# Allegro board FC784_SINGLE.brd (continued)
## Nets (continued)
IO316: TP316.1(TP) U1.AD3(IO316)
IO317: TP317.1(TP) U1.AD4(IO317)
IO318: TP318.1(TP) U1.AD5(IO318)
IO319: TP319.1(TP) U1.AD6(IO319)
IO320: TP320.1(TP) U1.AD8(IO320)
IO321: TP321.1(TP) U1.AD9(IO321)
IO322: TP322.1(TP) U1.AD10(IO322)
IO323: TP323.1(TP) U1.AD11(IO323)
IO324: TP324.1(TP) U1.AD13(IO324)
IO325: TP325.1(TP) U1.AD14(IO325)
IO326: TP326.1(TP) U1.AD15(IO326)
IO327: TP327.1(TP) U1.AD16(IO327)
IO328: TP328.1(TP) U1.AD18(IO328)
IO329: TP329.1(TP) U1.AD19(IO329)
IO330: TP330.1(TP) U1.AD20(IO330)
IO331: TP331.1(TP) U1.AD21(IO331)
IO332: TP332.1(TP) U1.AE1(IO332)
IO333: TP333.1(TP) U1.AE2(IO333)
IO334: TP334.1(TP) U1.AE3(IO334)
IO335: TP335.1(TP) U1.AE5(IO335)
IO336: TP336.1(TP) U1.AE6(IO336)
IO337: TP337.1(TP) U1.AE7(IO337)
IO338: TP338.1(TP) U1.AE8(IO338)
IO339: TP339.1(TP) U1.AE10(IO339)
IO340: TP340.1(TP) U1.AE11(IO340)
IO341: TP341.1(TP) U1.AE12(IO341)
IO342: TP342.1(TP) U1.AE13(IO342)
IO343: TP343.1(TP) U1.AE15(IO343)
IO344: TP344.1(TP) U1.AE16(IO344)
IO345: TP345.1(TP) U1.AE17(IO345)
IO346: TP346.1(TP) U1.AE18(IO346)
IO347: TP347.1(TP) U1.AE20(IO347)
IO348: TP348.1(TP) U1.AE21(IO348)
IO349: TP349.1(TP) U1.AF1(IO349)
IO350: TP350.1(TP) U1.AF2(IO350)
IO351: TP351.1(TP) U1.AF3(IO351)
IO352: TP352.1(TP) U1.AF4(IO352)
IO353: TP353.1(TP) U1.AF5(IO353)
IO354: TP354.1(TP) U1.AF7(IO354)
IO355: TP355.1(TP) U1.AF8(IO355)
IO356: TP356.1(TP) U1.AF9(IO356)
IO357: TP357.1(TP) U1.AF10(IO357)
IO358: TP358.1(TP) U1.AF12(IO358)
IO359: TP359.1(TP) U1.AF13(IO359)
IO360: TP360.1(TP) U1.AF14(IO360)
IO361: TP361.1(TP) U1.AF15(IO361)
IO362: TP362.1(TP) U1.AF17(IO362)
IO363: TP363.1(TP) U1.AF18(IO363)
IO364: TP364.1(TP) U1.AF19(IO364)
IO365: TP365.1(TP) U1.AF20(IO365)
IO366: TP366.1(TP) U1.AG1(IO366)
IO367: TP367.1(TP) U1.AG2(IO367)
IO368: TP368.1(TP) U1.AG4(IO368)
IO369: TP369.1(TP) U1.AG5(IO369)
IO370: TP370.1(TP) U1.AG6(IO370)
IO371: TP371.1(TP) U1.AG7(IO371)
IO372: TP372.1(TP) U1.AG9(IO372)
IO373: TP373.1(TP) U1.AG10(IO373)
IO374: TP374.1(TP) U1.AG11(IO374)
IO375: TP375.1(TP) U1.AG12(IO375)
IO376: TP376.1(TP) U1.AG14(IO376)
IO377: TP377.1(TP) U1.AG15(IO377)
IO378: TP378.1(TP) U1.AG16(IO378)
IO379: TP379.1(TP) U1.AG17(IO379)
IO380: TP380.1(TP) U1.AG19(IO380)
IO381: TP381.1(TP) U1.AG20(IO381)
IO382: TP382.1(TP) U1.AG21(IO382)
IO383: TP383.1(TP) U1.AG22(IO383)
IO384: TP384.1(TP) U1.AH2(IO384)
IO385: TP385.1(TP) U1.AH3(IO385)
IO386: TP386.1(TP) U1.AH4(IO386)
IO387: TP387.1(TP) U1.AH6(IO387)
IO388: TP388.1(TP) U1.AH7(IO388)
IO389: TP389.1(TP) U1.AH8(IO389)
IO390: TP390.1(TP) U1.AH9(IO390)
IO391: TP391.1(TP) U1.AH11(IO391)
IO392: TP392.1(TP) U1.AH12(IO392)
IO393: TP393.1(TP) U1.AH13(IO393)
IO394: TP394.1(TP) U1.AH14(IO394)
IO395: TP395.1(TP) U1.AH16(IO395)
IO396: TP396.1(TP) U1.AH17(IO396)
IO397: TP397.1(TP) U1.AH18(IO397)
IO398: TP398.1(TP) U1.AH19(IO398)
IO399: TP399.1(TP) U1.AH21(IO399)
IO400: TP400.1(TP) U1.AH22(IO400)
IO401: TP401.1(TP) U1.AH23(IO401)
SERDES_0_INT_REFCLK_N: TP419.1(TP) U1.R24(SERDES_0_INT_REFCLK_N)
SERDES_0_INT_REFCLK_P: TP418.1(TP) U1.R23(SERDES_0_INT_REFCLK_P)
SERDES_0_RX0_N: TP403.1(TP) U1.T26(SERDES_0_RX0_N)
SERDES_0_RX0_P: TP402.1(TP) U1.T25(SERDES_0_RX0_P)
SERDES_0_RX1_N: TP405.1(TP) U1.V26(SERDES_0_RX1_N)
SERDES_0_RX1_P: TP404.1(TP) U1.V25(SERDES_0_RX1_P)
SERDES_0_RX2_N: TP407.1(TP) U1.Y26(SERDES_0_RX2_N)
SERDES_0_RX2_P: TP406.1(TP) U1.Y25(SERDES_0_RX2_P)
SERDES_0_RX3_N: TP409.1(TP) U1.AB26(SERDES_0_RX3_N)
SERDES_0_RX3_P: TP408.1(TP) U1.AB25(SERDES_0_RX3_P)
SERDES_0_TX0_N: TP411.1(TP) U1.R28(SERDES_0_TX0_N)
SERDES_0_TX0_P: TP410.1(TP) U1.R27(SERDES_0_TX0_P)
SERDES_0_TX1_N: TP412.1(TP) U1.U28(SERDES_0_TX1_N)
SERDES_0_TX1_P: TP413.1(TP) U1.U27(SERDES_0_TX1_P)
SERDES_0_TX2_N: TP415.1(TP) U1.W28(SERDES_0_TX2_N)
SERDES_0_TX2_P: TP414.1(TP) U1.W27(SERDES_0_TX2_P)
SERDES_0_TX3_N: TP417.1(TP) U1.AA28(SERDES_0_TX3_N)
SERDES_0_TX3_P: TP416.1(TP) U1.AA27(SERDES_0_TX3_P)
SERDES_0N_EXT_REFCLK_N: TP483.1(TP) U1.T22(SERDES_0N_EXT_REFCLK_N)
SERDES_0N_EXT_REFCLK_P: TP482.1(TP) U1.T21(SERDES_0N_EXT_REFCLK_P)
SERDES_0S_EXT_REFCLK_N: TP485.1(TP) U1.P22(SERDES_0S_EXT_REFCLK_N)
SERDES_0S_EXT_REFCLK_P: TP484.1(TP) U1.P21(SERDES_0S_EXT_REFCLK_P)
SERDES_01_EXT_REFCLK_N: TP475.1(TP) U1.N24(SERDES_01_EXT_REFCLK_N)
SERDES_01_EXT_REFCLK_P: TP474.1(TP) U1.N23(SERDES_01_EXT_REFCLK_P)
SERDES_1_INT_REFCLK_N: TP437.1(TP) U1.M22(SERDES_1_INT_REFCLK_N)
SERDES_1_INT_REFCLK_P: TP436.1(TP) U1.M21(SERDES_1_INT_REFCLK_P)
SERDES_1_RX0_N: TP421.1(TP) U1.H25(SERDES_1_RX0_N)
SERDES_1_RX0_P: TP420.1(TP) U1.H26(SERDES_1_RX0_P)
SERDES_1_RX1_N: TP422.1(TP) U1.K25(SERDES_1_RX1_N)
SERDES_1_RX1_P: TP423.1(TP) U1.K26(SERDES_1_RX1_P)
SERDES_1_RX2_N: TP425.1(TP) U1.M25(SERDES_1_RX2_N)
SERDES_1_RX2_P: TP424.1(TP) U1.M26(SERDES_1_RX2_P)
SERDES_1_RX3_N: TP427.1(TP) U1.P25(SERDES_1_RX3_N)
SERDES_1_RX3_P: TP426.1(TP) U1.P26(SERDES_1_RX3_P)
SERDES_1_TX0_N: TP429.1(TP) U1.G27(SERDES_1_TX0_N)
SERDES_1_TX0_P: TP428.1(TP) U1.G28(SERDES_1_TX0_P)
SERDES_1_TX1_N: TP430.1(TP) U1.J27(SERDES_1_TX1_N)
SERDES_1_TX1_P: TP431.1(TP) U1.J28(SERDES_1_TX1_P)
SERDES_1_TX2_N: TP433.1(TP) U1.L27(SERDES_1_TX2_N)
SERDES_1_TX2_P: TP432.1(TP) U1.L28(SERDES_1_TX2_P)
SERDES_1_TX3_N: TP435.1(TP) U1.N27(SERDES_1_TX3_N)
SERDES_1_TX3_P: TP434.1(TP) U1.N28(SERDES_1_TX3_P)
SERDES_02_EXT_REFCLK_N: TP476.1(TP) U1.U24(SERDES_02_EXT_REFCLK_N)
SERDES_02_EXT_REFCLK_P: TP477.1(TP) U1.U23(SERDES_02_EXT_REFCLK_P)
SERDES_2_INT_REFCLK_N: TP455.1(TP) U1.W24(SERDES_2_INT_REFCLK_N)
SERDES_2_INT_REFCLK_P: TP454.1(TP) U1.W23(SERDES_2_INT_REFCLK_P)
SERDES_2_RX0_N: TP439.1(TP) U1.AC23(SERDES_2_RX0_P)
SERDES_2_RX0_P: TP438.1(TP) U1.AC24(SERDES_2_RX0_N)
SERDES_2_RX1_N: TP440.1(TP) U1.AF26(SERDES_2_RX1_N)
SERDES_2_RX1_P: TP441.1(TP) U1.AF25(SERDES_2_RX1_P)
SERDES_2_RX2_N: TP443.1(TP) U1.AD26(SERDES_2_RX2_N)
SERDES_2_RX2_P: TP442.1(TP) U1.AD25(SERDES_2_RX2_P)
SERDES_2_RX3_N: TP445.1(TP) U1.AE24(SERDES_2_RX3_N)
SERDES_2_RX3_P: TP444.1(TP) U1.AE23(SERDES_2_RX3_P)
SERDES_2_TX0_N: TP447.1(TP) U1.AC28(SERDES_2_TX0_N)
SERDES_2_TX0_P: TP446.1(TP) U1.AC27(SERDES_2_TX0_P)
SERDES_2_TX1_N: TP448.1(TP) U1.AH26(SERDES_2_TX1_N)
SERDES_2_TX1_P: TP449.1(TP) U1.AH25(SERDES_2_TX1_P)
SERDES_2_TX2_N: TP451.1(TP) U1.AE28(SERDES_2_TX2_N)
SERDES_2_TX2_P: TP450.1(TP) U1.AE27(SERDES_2_TX2_P)
SERDES_2_TX3_N: TP453.1(TP) U1.AG28(SERDES_2_TX3_N)
SERDES_2_TX3_P: TP452.1(TP) U1.AG27(SERDES_2_TX3_P)
SERDES_3_INT_REFCLK_N: TP473.1(TP) U1.J24(SERDES_3_INT_REFCLK_N)
SERDES_3_INT_REFCLK_P: TP472.1(TP) U1.J23(SERDES_3_INT_REFCLK_P)
SERDES_3_RX0_N: TP457.1(TP) U1.B25(SERDES_3_RX0_N)
SERDES_3_RX0_P: TP456.1(TP) U1.B26(SERDES_3_RX0_P)
SERDES_3_RX1_N: TP458.1(TP) U1.D25(SERDES_3_RX1_N)
SERDES_3_RX1_P: TP459.1(TP) U1.D26(SERDES_3_RX1_P)
SERDES_3_RX2_N: TP461.1(TP) U1.C23(SERDES_3_RX2_N)
SERDES_3_RX2_P: TP460.1(TP) U1.C24(SERDES_3_RX2_P)
SERDES_3_RX3_N: TP463.1(TP) U1.F25(SERDES_3_RX3_N)
SERDES_3_RX3_P: TP462.1(TP) U1.F26(SERDES_3_RX3_P)
SERDES_3_TX0_N: TP465.1(TP) U1.A27(SERDES_3_TX0_N)
SERDES_3_TX0_P: TP464.1(TP) U1.A28(SERDES_3_TX0_P)
SERDES_3_TX1_N: TP466.1(TP) U1.C27(SERDES_3_TX1_N)
SERDES_3_TX1_P: TP467.1(TP) U1.C28(SERDES_3_TX1_P)
SERDES_3_TX2_N: TP469.1(TP) U1.A23(SERDES_3_TX2_N)
SERDES_3_TX2_P: TP468.1(TP) U1.A24(SERDES_3_TX2_P)
SERDES_3_TX3_N: TP471.1(TP) U1.E27(SERDES_3_TX3_N)
SERDES_3_TX3_P: TP470.1(TP) U1.E28(SERDES_3_TX3_P)
SERDES_13_EXT_REFCLK_N: TP479.1(TP) U1.L24(SERDES_13_EXT_REFCLK_N)
SERDES_13_EXT_REFCLK_P: TP478.1(TP) U1.L23(SERDES_13_EXT_REFCLK_P)
SERDES_24_EXT_REFCLK_N: TP487.1(TP) U1.AA24(SERDES_24_EXT_REFCLK_N)
SERDES_24_EXT_REFCLK_P: TP486.1(TP) U1.AA23(SERDES_24_EXT_REFCLK_P)
SERDES_35_EXT_REFCLK_N: TP488.1(TP) U1.G24(SERDES_35_EXT_REFCLK_N)
SERDES_35_EXT_REFCLK_P: TP489.1(TP) U1.G23(SERDES_35_EXT_REFCLK_P)
SERDES_VREF: U1.F22(SERDES_VREF1) U1.H22(SERDES_VREF2)

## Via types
v1: diameter 0.457, hole 0.254, TOP to BOTTOM, 643 vias

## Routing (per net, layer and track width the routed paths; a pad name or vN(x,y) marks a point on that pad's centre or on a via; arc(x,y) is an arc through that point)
GND: length 118.8
  TOP w0.254: U1.E25 v1(65.81,69.23) ; U1.AH24 v1(64.81,45.23) ; U1.J2 v1(41.81,65.23) ; U1.AH28 v1(68.81,45.23) ; U1.AA6 v1(45.81,52.23) ; U1.AB27 v1(67.81,51.23) ; U1.AG8 v1(47.81,46.23) ; U1.D28 v1(68.81,70.23) ; U1.AE4 v1(43.81,48.23) ; U1.K14 v1(53.81,64.23) ; U1.N13 v1(52.81,61.23) ; U1.A6 v1(46.31,73.44) ; U1.V18 v1(58.81,55.23) ; U1.Y9 v1(48.81,53.23) ; U1.V16 v1(56.81,55.23) ; U1.H5 v1(44.81,66.23) ; U1.D24 v1(64.81,70.23) ; U1.P12 v1(51.81,60.23) ; U1.AH27 v1(67.81,45.23) ; U1.T18 v1(58.81,57.23) ; U1.E14 v1(53.81,69.23) ; U1.AC20 v1(60.81,50.23) ; U1.P27 v1(67.81,60.23) ; U1.J25 v1(65.81,65.23) ; U1.V24 v1(64.81,55.23) ; U1.AE22 v1(62.81,48.23) ; U1.AD22 v1(62.81,49.23) ; U1.M14 v1(53.81,62.23) ; U1.V22 v1(62.81,55.23) ; U1.U13 v1(52.81,56.23) ; U1.U15 v1(55.81,56.23) ; U1.K24 v1(64.81,64.23) ; U1.E22 v1(62.81,69.23) ; U1.T24 v1(64.81,57.23) ; U1.V20 v1(60.81,55.23) ; U1.L11 v1(50.81,63.23) ; U1.K9 v1(48.81,64.23) ; U1.V27 v1(67.81,55.23) ; U1.U19 v1(59.81,56.23) ; U1.A16 v1(56.31,73.44) ; U1.L17 v1(57.81,63.23) ; U1.AG23 v1(62.81,46.23) ; U1.V21 v1(61.81,55.23) ; U1.U25 v1(65.81,56.23) ; U1.R25 v1(64.81,59.23) ; U1.AH5 v1(45.31,45.03) ; U1.AC10 v1(49.81,50.23) ; U1.F24 v1(64.81,68.23) ; U1.AF27 v1(67.81,47.23) ; U1.F1 v1(40.61,67.73) ; U1.Y27 v1(67.81,53.23) ; U1.L15 v1(55.81,63.23) ; U1.C20 v1(60.81,71.23) ; U1.AE14 v1(53.81,48.23) ; U1.M27 v1(67.81,62.23) ; U1.F11 v1(50.81,68.23) ; U1.B24 v1(64.81,72.23) ; U1.D22 v1(62.81,70.23) ; U1.AA16 v1(56.81,52.23) ; U1.K27 v1(67.81,64.23) ; U1.U11 v1(50.81,56.23) ; U1.N25 v1(65.81,61.23) ; U1.W22 v1(62.81,54.23) ; U1.D7 v1(46.81,70.23) ; U1.P7 v1(46.81,60.23) ; U1.AG25 v1(65.81,46.23) ; U1.P16 v1(56.81,60.23) ; U1.U17 v1(57.81,56.23) ; U1.R17 v1(56.81,59.23) ; U1.Y22 v1(62.81,53.23) ; U1.B3 v1(42.81,72.23) ; U1.AC22 v1(62.81,50.23) ; U1.AG24 v1(64.81,46.23) ; U1.F28 v1(68.81,68.23) ; U1.R19 v1(58.81,59.23) ; U1.A25 v1(64.81,73.23) ; U1.T20 v1(60.81,57.23) ; U1.AF11 v1(50.81,47.23) ; U1.AG18 v1(57.81,46.23) ; U1.M24 v1(64.81,62.23) ; U1.B13 v1(52.81,72.23) ; U1.B28 v1(68.81,72.23) ; U1.U8 v1(47.81,56.23) ; U1.T28 v1(68.81,57.23) ; U1.K20 v1(60.81,64.23) ; U1.AD17 v1(57.81,49.23) ; U1.E24 v1(64.81,69.23) ; U1.N22 v1(62.81,61.23) ; U1.AB24 v1(64.81,51.23) ; U1.M12 v1(51.81,62.23) ; U1.J22 v1(62.81,65.23) ; U1.T27 v1(67.81,57.23) ; U1.L25 v1(65.81,63.23) ; U1.L19 v1(59.81,63.23) ; U1.G8 v1(47.81,67.23) ; U1.K28 v1(68.81,64.23) ; U1.AB22 v1(62.81,51.23) ; U1.M18 v1(58.81,62.23) ; U1.R13 v1(52.81,58.23) ; U1.T14 v1(53.81,57.23) ; U1.H24 v1(64.81,66.23) ; U1.H27 v1(67.81,66.23) ; U1.Y24 v1(64.81,53.23) ; U1.W2 v1(41.81,54.23) ; U1.N19 v1(59.81,61.23) ; U1.G18 v1(58.81,67.23) ; U1.C10 v1(49.81,71.23) ; U1.E23 v1(63.81,69.23) ; U1.M16 v1(56.81,62.23) ; U1.AE25 v1(65.81,48.23) ; U1.V5 v1(44.81,55.23) ; U1.K21 v1(61.81,64.23) ; U1.F27 v1(67.81,68.23) ; U1.P20 v1(60.81,60.23) ; U1.W25 v1(65.81,54.23) ; U1.V28 v1(68.81,55.23) ; U1.AB13 v1(52.81,51.23) ; U1.AB28 v1(68.81,51.23) ; U1.V14 v1(53.81,55.23) ; U1.K22 v1(62.81,64.23) ; U1.N17 v1(57.81,61.23) ; U1.N11 v1(50.81,61.23) ; U1.AH15 v1(55.31,45.03) ; U1.R15 v1(54.81,59.23) ; U1.E4 v1(43.81,69.23) ; U1.C22 v1(62.81,71.23) ; U1.AD24 v1(64.81,49.23) ; U1.H28 v1(68.81,66.23) ; U1.H15 v1(55.81,66.23) ; U1.AD7 v1(46.81,49.23) ; U1.P14 v1(53.81,60.23) ; U1.AF21 v1(60.81,47.23) ; U1.M3 v1(42.81,62.23) ; U1.AB3 v1(42.81,51.23) ; U1.AF22 v1(61.81,47.23) ; U1.A22 v1(62.81,73.23) ; U1.T1 v1(40.61,57.73) ; U1.L13 v1(52.81,63.23) ; U1.R4 v1(43.81,58.23) ; U1.AD28 v1(68.81,49.23) ; U1.B27 v1(67.81,72.23) ; U1.M20 v1(60.81,62.23) ; U1.Y19 v1(59.81,53.23) ; U1.AF24 v1(64.81,47.23) ; U1.AD27 v1(67.81,49.23) ; U1.G25 v1(65.81,67.23) ; U1.D27 v1(67.81,70.23) ; U1.N15 v1(55.81,61.23) ; U1.G22 v1(62.81,67.23) ; U1.D17 v1(57.81,70.23) ; U1.V12 v1(51.81,55.23) ; U1.P18 v1(58.81,60.23) ; U1.L6 v1(45.81,63.23) ; U1.Y28 v1(68.81,53.23) ; U1.M28 v1(68.81,62.23) ; U1.R22 v1(61.81,59.23) ; U1.B22 v1(61.81,72.23) ; U1.AA22 v1(62.81,52.23) ; U1.AH1 v1(40.81,45.23) ; U1.AA25 v1(65.81,52.23) ; U1.R11 v1(50.81,58.23) ; U1.AC25 v1(65.81,50.23) ; U1.C25 v1(65.81,71.23) ; U1.AF28 v1(68.81,47.23) ; U1.A26 v1(65.81,73.23) ; U1.P28 v1(68.81,60.23) ; U1.T16 v1(56.81,57.23) ; U1.T12 v1(51.81,57.23)
VDD: length 14.8
  TOP w0.254: U1.M15 v1(55.81,62.23) ; U1.P15 v1(55.81,60.23) ; U1.P17 v1(57.81,60.23) ; U1.T19 v1(59.81,57.23) ; U1.P19 v1(59.81,60.23) ; U1.N16 v1(56.81,61.23) ; U1.T17 v1(57.81,57.23) ; U1.M19 v1(59.81,62.23) ; U1.U16 v1(56.81,56.23) ; U1.P13 v1(52.81,60.23) ; U1.T15 v1(55.81,57.23) ; U1.N20 v1(60.81,61.23) ; U1.R18 v1(57.81,59.23) ; U1.R20 v1(59.81,59.23) ; U1.T13 v1(52.81,57.23) ; U1.N18 v1(58.81,61.23) ; U1.U14 v1(53.81,56.23) ; U1.M17 v1(57.81,62.23) ; U1.N14 v1(53.81,61.23) ; U1.U18 v1(58.81,56.23) ; U1.R14 v1(53.81,58.23)
VDD18: length 4.2
  TOP w0.254: U1.V17 v1(57.81,55.23) ; U1.W21 v1(61.81,54.23) ; U1.V19 v1(59.81,55.23) ; U1.V15 v1(55.81,55.23) ; U1.W11 v1(50.81,54.23) ; U1.V13 v1(52.81,55.23)
VDD25: length 3.5
  TOP w0.254: U1.M13 v1(52.81,62.23) ; U1.L20 v1(60.81,63.23) ; U1.R16 v1(55.81,59.23) ; U1.U20 v1(60.81,56.23) ; U1.U12 v1(51.81,56.23)
VDDA: length 17
  TOP w0.254: U1.E26 v1(66.81,69.23) ; U1.T23 v1(63.81,57.23) ; U1.W26 v1(66.81,54.23) ; U1.AB23 v1(63.81,51.23) ; U1.AC26 v1(66.81,50.23) ; U1.B23 v1(62.81,72.23) ; U1.P24 v1(64.81,60.23) ; U1.C26 v1(66.81,71.23) ; U1.AA26 v1(66.81,52.23) ; U1.R26 v1(65.81,59.23) ; U1.H23 v1(63.81,66.23) ; U1.AD23 v1(63.81,49.23) ; U1.AF23 v1(62.81,47.23) ; U1.AE26 v1(66.81,48.23) ; U1.Y23 v1(63.81,53.23) ; U1.D23 v1(63.81,70.23) ; U1.G26 v1(66.81,67.23) ; U1.F23 v1(63.81,68.23) ; U1.U26 v1(66.81,56.23) ; U1.M23 v1(63.81,62.23) ; U1.N26 v1(66.81,61.23) ; U1.AG26 v1(66.81,46.23) ; U1.L26 v1(66.81,63.23) ; U1.J26 v1(66.81,65.23)
VDDA25: length 2.8
  TOP w0.254: U1.U22 v1(62.81,56.23) ; U1.N21 v1(61.81,61.23) ; U1.R21 v1(60.81,59.23) ; U1.L22 v1(62.81,63.23)
VDDAUX2: length 3.5
  TOP w0.254: U1.L16 v1(56.81,63.23) ; U1.K11 v1(50.81,64.23) ; U1.L14 v1(53.81,63.23) ; U1.K15 v1(55.81,64.23) ; U1.L18 v1(58.81,63.23)
VDDAUX4: length 2.8
  TOP w0.254: U1.V11 v1(50.81,55.23) ; U1.R12 v1(51.81,58.23) ; U1.P11 v1(50.81,60.23) ; U1.T11 v1(50.81,57.23)
VDDAUX5: length 2.1
  TOP w0.254: U1.M11 v1(50.81,62.23) ; U1.N12 v1(51.81,61.23) ; U1.L12 v1(51.81,63.23)
VDDI0: length 6.4
  TOP w0.254: U1.AE9 v1(48.81,48.23) ; U1.AG3 v1(42.81,46.23) ; U1.AC5 v1(44.81,50.23) ; U1.AA11 v1(50.81,52.23) ; U1.AD2 v1(41.81,49.23) ; U1.AF6 v1(45.81,47.23) ; U1.AH10 v1(50.31,45.03) ; U1.AA1 v1(40.61,52.73) ; U1.AB8 v1(47.81,51.23)
VDDI1: length 4.9
  TOP w0.254: U1.AF16 v1(55.81,47.23) ; U1.W17 v1(57.81,54.23) ; U1.AH20 v1(60.31,45.03) ; U1.AB18 v1(58.81,51.23) ; U1.AE19 v1(59.81,48.23) ; U1.AA21 v1(61.81,52.23) ; U1.AC15 v1(55.81,50.23)
VDDI2: length 8.5
  TOP w0.254: U1.A21 v1(61.81,73.23) ; U1.F16 v1(56.81,68.23) ; U1.B8 v1(47.81,72.23) ; U1.A11 v1(51.31,73.44) ; U1.D12 v1(51.81,70.23) ; U1.B18 v1(57.81,72.23) ; U1.E9 v1(48.81,69.23) ; U1.J17 v1(57.81,65.23) ; U1.G13 v1(52.81,67.23) ; U1.H20 v1(60.81,66.23) ; U1.E19 v1(59.81,69.23) ; U1.C15 v1(55.81,71.23)
VDDI3: length 1.4
  TOP w0.254: U1.H10 v1(49.81,66.23) ; U1.K13 v1(52.81,64.23)
VDDI4: length 7.8
  TOP w0.254: U1.U3 v1(42.81,56.23) ; U1.U10 v1(49.81,56.23) ; U1.R9 v1(48.81,58.23) ; U1.M8 v1(47.81,62.23) ; U1.W7 v1(46.81,54.23) ; U1.L1 v1(40.61,62.73) ; U1.T6 v1(45.81,57.23) ; U1.K4 v1(43.81,64.23) ; U1.P2 v1(41.81,60.23) ; U1.N5 v1(44.81,61.23) ; U1.Y4 v1(43.81,53.23)
VDDI5: length 4.2
  TOP w0.254: U1.J7 v1(46.81,65.23) ; U1.G3 v1(42.81,67.23) ; U1.F6 v1(45.81,68.23) ; U1.A1 v1(40.81,73.23) ; U1.C5 v1(44.81,71.23) ; U1.D2 v1(41.81,70.23)
VDDI7: length 2.1
  TOP w0.254: U1.AD12 v1(51.81,49.23) ; U1.AG13 v1(52.81,46.23) ; U1.Y14 v1(53.81,53.23)
VDDSREF: length 3.5
  TOP w0.254: U1.L21 v1(61.81,63.23) ; U1.U21 v1(61.81,56.23) ; U1.V23 v1(63.81,55.23) ; U1.K23 v1(63.81,64.23) ; U1.P23 v1(63.81,60.23)
IO1: length 1.6
  TOP w0.127: U1.A2 42.31,74.35
IO2: length 1.6
  TOP w0.127: U1.A3 43.31,74.35
IO3: length 1.6
  TOP w0.127: U1.A4 44.31,74.35
IO4: length 1.6
  TOP w0.127: U1.A5 45.31,74.35
IO5: length 1.6
  TOP w0.127: U1.A7 47.31,74.35
IO6: length 1.6
  TOP w0.127: U1.A8 48.31,74.35
IO7: length 1.6
  TOP w0.127: U1.A9 49.31,74.35
IO8: length 1.6
  TOP w0.127: U1.A10 50.31,74.35
IO9: length 1.6
  TOP w0.127: U1.A12 52.31,74.35
IO10: length 1.6
  TOP w0.127: U1.A13 53.31,74.35
IO11: length 1.6
  TOP w0.127: U1.A14 54.31,74.35
IO12: length 1.6
  TOP w0.127: U1.A15 55.31,74.35
IO13: length 1.6
  TOP w0.127: U1.A17 57.31,74.35
IO14: length 1.6
  TOP w0.127: U1.A18 58.31,74.35
IO15: length 1.6
  TOP w0.127: U1.A19 59.31,74.35
IO16: length 1.6
  TOP w0.127: U1.A20 60.31,74.35
IO17: length 1.9
  TOP w0.127: U1.B1 39.42,71.73
IO18: length 3.1
  TOP w0.127: 39.42,72.23 41.81,72.23 U1.B2
IO19: length 2.8
  TOP w0.127: 43.81,74.35 43.81,72.23 U1.B4
IO20: length 2.8
  TOP w0.127: U1.B5 44.81,72.23 44.81,74.35
IO21: length 2.8
  TOP w0.127: 45.81,74.33 45.81,72.23 U1.B6
IO22: length 2.8
  TOP w0.127: 46.81,74.33 46.81,72.23 U1.B7
IO23: length 2.8
  TOP w0.127: 48.81,74.35 48.81,72.23 U1.B9
IO24: length 2.8
  TOP w0.127: 49.81,74.35 49.81,72.23 U1.B10
IO25: length 2.9
  TOP w0.127: 50.81,74.39 50.81,72.24 U1.B11
IO26: length 2.8
  TOP w0.127: U1.B12 51.81,72.23 51.81,74.35
IO27: length 2.8
  TOP w0.127: U1.B14 53.81,72.23 53.81,74.35
IO28: length 2.8
  TOP w0.127: 54.81,74.35 54.81,72.23 U1.B15
IO29: length 2.8
  TOP w0.127: 55.81,74.35 55.81,72.23 U1.B16
IO30: length 2.8
  TOP w0.127: U1.B17 56.83,72.21 56.83,74.32
IO31: length 2.8
  TOP w0.127: U1.B19 58.81,72.23 58.81,74.35
IO32: length 2.8
  TOP w0.127: 59.81,74.35 59.81,72.23 U1.B20
IO33: length 2.8
  TOP w0.127: 60.81,74.35 60.81,72.23 U1.B21
IO34: length 1.9
  TOP w0.127: U1.C1 39.42,70.73
IO35: length 3.1
  TOP w0.127: U1.C2 41.81,71.23 39.42,71.23
IO36: length 3.1
  TOP w0.254: U1.C3 v1(42.81,71.23)
  L3_SIG1 w0.102: v1(42.81,71.23) 42.26,71.78 42.26,73.42
IO37: length 2.9
  TOP w0.254: U1.C4 v1(43.81,71.23)
  L3_SIG1 w0.102: v1(43.81,71.23) 43.81,73.42
IO38: length 3.5
  TOP w0.254: U1.C6 v1(45.81,71.23)
  L3_SIG1 w0.102: v1(45.81,71.23) 45.81,71.77 45.33,72.26 45.33,73.84
IO39: length 3.5
  TOP w0.254: U1.C7 v1(46.81,71.23)
  L3_SIG1 w0.102: v1(46.81,71.23) 46.81,74.02
IO40: length 3.5
  TOP w0.254: U1.C8 v1(47.81,71.23)
  L3_SIG1 w0.102: 48.31,73.79 48.31,71.73 v1(47.81,71.23)
IO41: length 3.3
  TOP w0.254: U1.C9 v1(48.81,71.23)
  L3_SIG1 w0.102: v1(48.81,71.23) 48.81,73.87
IO42: length 3.7
  TOP w0.254: U1.C11 v1(50.81,71.23)
  L3_SIG1 w0.102: v1(50.81,71.23) 50.81,72.04 50.3,72.55 50.3,74.04
IO43: length 3.5
  TOP w0.254: U1.C12 v1(51.81,71.23)
  L3_SIG1 w0.102: v1(51.81,71.23) 51.81,74.06
IO44: length 3.7
  TOP w0.254: U1.C13 v1(52.81,71.23)
  L3_SIG1 w0.102: 53.32,74.02 53.32,72.04 52.81,71.53 v1(52.81,71.23)
IO45: length 3.6
  TOP w0.254: U1.C14 v1(53.81,71.23)
  L3_SIG1 w0.102: 54.19,73.99 54.19,71.61 v1(53.81,71.23)
IO46: length 3.9
  TOP w0.254: U1.C16 v1(56.81,71.23)
  L3_SIG1 w0.102: 55.82,74.04 55.82,72.47 56.81,71.47 v1(56.81,71.23)
IO47: length 3.8
  TOP w0.254: U1.C17 v1(57.81,71.23)
  L3_SIG1 w0.102: 57.31,74.16 57.31,72 57.81,71.5 v1(57.81,71.23)
IO48: length 3.5
  TOP w0.254: U1.C18 v1(58.81,71.23)
  L3_SIG1 w0.102: v1(58.81,71.23) 58.81,74.01
IO49: length 2.9
  TOP w0.254: U1.C19 v1(59.81,71.23)
  L3_SIG1 w0.102: v1(59.81,71.23) 59.81,73.4
IO50: length 3.5
  TOP w0.254: U1.C21 v1(61.81,71.23)
  L3_SIG1 w0.102: v1(61.81,71.23) 61.81,71.53 61.28,72.06 61.28,73.78
IO51: length 1.9
  TOP w0.127: U1.D1 39.42,69.73
IO52: length 4.6
  TOP w0.254: U1.D3 v1(42.81,70.23)
  L3_SIG1 w0.102: 39.09,69.73 42.31,69.73 v1(42.81,70.23)
IO53: length 4.1
  TOP w0.254: U1.D4 v1(43.81,70.23)
  L3_SIG1 w0.102: v1(43.81,70.23) 43.81,70.52 43.31,71.02 43.31,73.45
IO54: length 3.9
  TOP w0.254: U1.D5 v1(44.81,70.23)
  L3_SIG1 w0.102: 44.31,73.27 44.31,70.73 v1(44.81,70.23)
IO55: length 4.7
  TOP w0.254: U1.D6 v1(45.81,70.23)
  L3_SIG1 w0.102: 45.8,73.85 45.8,72.5 46.31,71.99 46.31,70.73 v1(45.81,70.23)
IO56: length 4.6
  TOP w0.254: U1.D8 v1(47.81,70.23)
  L3_SIG1 w0.102: v1(47.81,70.23) 47.31,70.73 47.31,73.95
IO57: length 4.4
  TOP w0.254: U1.D9 v1(48.81,70.23)
  L3_SIG1 w0.102: v1(48.81,70.23) 49.31,70.73 49.31,73.74
IO58: length 4.9
  TOP w0.254: U1.D10 v1(49.81,70.23)
  L3_SIG1 w0.102: v1(49.81,70.23) 50.31,70.73 50.31,71.66 49.74,72.23 49.74,74.03
IO59: length 4.9
  TOP w0.254: U1.D11 v1(50.81,70.23)
  L3_SIG1 w0.102: v1(50.81,70.23) 51.31,70.73 51.31,72.47 50.79,72.98 50.79,74.03
IO60: length 4.8
  TOP w0.254: U1.D13 v1(52.81,70.23)
  L3_SIG1 w0.102: v1(52.81,70.23) 53.31,70.73 53.31,71.45 53.77,71.91 53.77,73.95
IO61: length 4.8
  TOP w0.254: U1.D14 v1(53.81,70.23)
  L3_SIG1 w0.102: 54.57,73.97 54.57,70.99 v1(53.81,70.23)
IO62: length 4.6
  TOP w0.254: U1.D15 v1(55.81,70.23)
  L3_SIG1 w0.102: 55,73.81 55,71.04 v1(55.81,70.23)
IO63: length 5.1
  TOP w0.254: U1.D16 v1(56.81,70.23)
  L3_SIG1 w0.102: 55.4,74.07 55.4,72.35 56.31,71.43 56.31,70.73 v1(56.81,70.23)
IO64: length 4.5
  TOP w0.254: U1.D18 v1(58.81,70.23)
  L3_SIG1 w0.102: 58.31,73.78 58.31,70.73 v1(58.81,70.23)
IO65: length 4.5
  TOP w0.254: U1.D19 v1(59.81,70.23)
  L3_SIG1 w0.102: 59.31,73.84 59.31,70.73 v1(59.81,70.23)
IO66: length 3.9
  TOP w0.254: U1.D20 v1(60.81,70.23)
  L3_SIG1 w0.102: 60.31,73.26 60.31,70.73 v1(60.81,70.23)
IO67: length 4.7
  TOP w0.254: U1.D21 v1(61.81,70.23)
  L3_SIG1 w0.102: v1(61.81,70.23) 61.31,70.73 61.31,71.44 60.71,72.04 60.71,73.77
IO68: length 1.9
  TOP w0.127: U1.E1 39.42,68.73
IO69: length 3.1
  TOP w0.127: 39.42,69.23 41.81,69.23 U1.E2
IO70: length 4.4
  TOP w0.254: U1.E3 v1(42.81,69.23)
  L3_SIG1 w0.102: v1(42.81,69.23) 39.09,69.23
IO71: length 7.3
  TOP w0.254: U1.E5 v1(44.81,69.23)
  L3_SIG1 w0.102: 39.1,70.73 43.02,70.73 43.31,70.45 43.31,70.03 43.61,69.73 44.31,69.73 44.8,69.23 v1(44.81,69.23)
IO72: length 5.6
  TOP w0.254: U1.E6 v1(45.81,69.23)
  L3_SIG1 w0.102: 44.89,73.75 44.89,72.04 45.32,71.62 45.32,69.73 v1(45.81,69.23)
IO73: length 7.5
  TOP w0.254: U1.E7 v1(46.81,69.23)
  L4_SIG2 w0.102: v1(46.81,69.23) 46.81,69.53 46.31,70.03 46.31,72.6 45.76,73.16 45.76,75.55
IO74: length 7.3
  TOP w0.254: U1.E8 v1(47.81,69.23)
  L4_SIG2 w0.102: v1(47.81,69.23) 47.31,69.73 47.31,75.64
IO75: length 7.3
  TOP w0.254: U1.E10 v1(49.81,69.23)
  L4_SIG2 w0.102: 49.31,75.64 49.31,69.73 v1(49.81,69.23)
IO76: length 7.5
  TOP w0.254: U1.E11 v1(50.81,69.23)
  L4_SIG2 w0.102: 50.63,75.53 50.63,73.15 51.31,72.47 51.31,69.73 v1(50.81,69.23)
IO77: length 5.7
  TOP w0.254: U1.E12 v1(51.81,69.23)
  L3_SIG1 w0.102: 52.31,74.05 52.31,69.73 v1(51.81,69.23)
IO78: length 7.3
  TOP w0.254: U1.E13 v1(52.81,69.23)
  L4_SIG2 w0.102: 53.31,75.64 53.31,69.73 v1(52.81,69.23)
IO79: length 7.3
  TOP w0.254: U1.E15 v1(55.81,69.23)
  L4_SIG2 w0.102: v1(55.81,69.23) 55.31,69.73 55.31,75.64
IO80: length 7.5
  TOP w0.254: U1.E16 v1(56.81,69.23)
  L4_SIG2 w0.102: v1(56.81,69.23) 56.31,69.73 56.31,72.62 56.86,73.16 56.86,75.54
IO81: length 5.9
  TOP w0.254: U1.E17 v1(57.81,69.23)
  L3_SIG1 w0.102: v1(57.81,69.23) 57.32,69.73 57.32,71.51 56.85,71.98 56.85,74.03
IO82: length 7.3
  TOP w0.254: U1.E18 v1(58.81,69.23)
  L4_SIG2 w0.102: 58.31,75.64 58.31,69.73 v1(58.81,69.23)
IO83: length 7.3
  TOP w0.254: U1.E20 v1(60.81,69.23)
  L4_SIG2 w0.102: v1(60.81,69.23) 60.31,69.73 60.31,75.64
IO84: length 5.9
  TOP w0.254: U1.E21 v1(61.81,69.23)
  L3_SIG1 w0.102: 62.31,74.24 62.31,69.73 v1(61.81,69.23)
IO85: length 3.1
  TOP w0.127: U1.F2 41.83,68.21 39.42,68.21
IO86: length 4.4
  TOP w0.254: U1.F3 v1(42.81,68.23)
  L3_SIG1 w0.102: v1(42.81,68.23) 39.11,68.23
IO87: length 5.6
  TOP w0.254: U1.F4 v1(43.81,68.23)
  L3_SIG1 w0.102: v1(43.81,68.23) 43.31,68.73 39.09,68.73
IO88: length 6.5
  TOP w0.254: U1.F5 v1(44.81,68.23)
  L4_SIG2 w0.102: v1(44.81,68.23) 44.52,68.23 44.02,68.73 39.26,68.73
IO89: length 9.5
  TOP w0.254: U1.F7 v1(46.81,68.23)
  L4_SIG2 w0.102: v1(46.81,68.23) 46.53,68.23 46.03,68.73 45.6,68.73 45.31,69.03 45.31,69.44 45.02,69.73 44.52,69.73 44.31,69.94 44.31,75.31
IO90: length 9.8
  TOP w0.254: U1.F8 v1(47.81,68.23)
  L4_SIG2 w0.102: 44.89,75.45 44.89,72.98 45.31,72.56 45.31,69.96 45.55,69.73 46.05,69.73 46.31,69.47 46.31,69.03 46.61,68.73 47.31,68.73 v1(47.81,68.23)
IO91: length 8.3
  TOP w0.254: U1.F9 v1(48.81,68.23)
  L4_SIG2 w0.102: v1(48.81,68.23) 48.31,68.73 48.31,75.64
IO92: length 8.3
  TOP w0.254: U1.F10 v1(49.81,68.23)
  L4_SIG2 w0.102: v1(49.81,68.23) 50.31,68.73 50.31,72.46 49.89,72.88 49.89,75.49
IO93: length 8.4
  TOP w0.254: U1.F12 v1(51.81,68.23)
  L4_SIG2 w0.102: v1(51.81,68.23) 52.31,68.73 52.31,75.67
IO94: length 8.4
  TOP w0.254: U1.F13 v1(52.81,68.23)
  L5_SIG3 w0.102: v1(52.81,68.23) 52.31,68.73 52.31,75.67
IO95: length 8.3
  TOP w0.254: U1.F14 v1(53.81,68.23)
  L4_SIG2 w0.102: 54.31,75.64 54.31,68.73 v1(53.81,68.23)
IO96: length 8.5
  TOP w0.254: U1.F15 v1(55.81,68.23)
  L4_SIG2 w0.102: v1(55.81,68.23) 54.98,69.07 54.98,75.64
IO97: length 8.3
  TOP w0.254: U1.F17 v1(57.81,68.23)
  L4_SIG2 w0.102: v1(57.81,68.23) 57.31,68.73 57.31,75.63
IO98: length 8.4
  TOP w0.254: U1.F18 v1(58.81,68.23)
  L5_SIG3 w0.102: 58.31,75.67 58.31,68.73 v1(58.81,68.23)
IO99: length 8.3
  TOP w0.254: U1.F19 v1(59.81,68.23)
  L4_SIG2 w0.102: v1(59.81,68.23) 59.31,68.73 59.31,75.64
IO100: length 6.9
  TOP w0.254: U1.F20 v1(60.81,68.23)
  L4_SIG2 w0.102: 61.31,74.2 61.31,68.73 v1(60.81,68.23)
IO101: length 8.3
  TOP w0.254: U1.F21 v1(61.81,68.23)
  L4_SIG2 w0.102: 62.31,75.65 62.31,68.73 v1(61.81,68.23)
IO102: length 1.9
  TOP w0.127: U1.G1 39.42,66.73
IO103: length 3.1
  TOP w0.127: 39.42,67.23 41.81,67.23 U1.G2
IO104: length 5.9
  TOP w0.254: U1.G4 v1(43.81,67.23)
  L3_SIG1 w0.102: v1(43.81,67.23) 43.31,67.73 42.21,67.73 41.64,67.17 39.09,67.17
IO105: length 6.5
  TOP w0.254: U1.G5 v1(44.81,67.23)
  L4_SIG2 w0.102: v1(44.81,67.23) 44.31,66.73 39.26,66.73
IO106: length 7.6
  TOP w0.254: U1.G6 v1(45.81,67.23)
  L4_SIG2 w0.102: 39.32,68.3 41.2,68.3 41.77,67.73 45.02,67.73 45.31,67.44 45.52,67.23 v1(45.81,67.23)
IO107: length 8.8
  TOP w0.254: U1.G7 v1(46.81,67.23)
  L4_SIG2 w0.102: v1(46.81,67.23) 46.31,67.73 45.61,67.73 45.31,68.03 45.31,68.49 45.07,68.73 44.56,68.73 44.31,68.98 44.31,69.44 44.02,69.73 40.27,69.73
IO108: length 8.4
  TOP w0.254: U1.G9 v1(48.81,67.23)
  L5_SIG3 w0.102: 48.31,74.67 48.31,68.02 48.81,67.52 v1(48.81,67.23)
IO109: length 8.2
  TOP w0.254: U1.G10 v1(49.81,67.23)
  L5_SIG3 w0.102: 49.31,74.5 49.31,67.73 v1(49.81,67.23)
IO110: length 8.4
  TOP w0.254: U1.G11 v1(50.81,67.23)
  L5_SIG3 w0.102: v1(50.81,67.23) 50.31,67.73 50.31,74.67
IO111: length 9.3
  TOP w0.254: U1.G12 v1(51.81,67.23)
  L5_SIG3 w0.102: v1(51.81,67.23) 51.31,67.73 51.31,72.24 51.85,72.78 51.85,75.4
IO112: length 9.5
  TOP w0.254: U1.G14 v1(53.81,67.23)
  L4_SIG2 w0.102: v1(53.81,67.23) 54.64,68.06 54.64,75.69
IO113: length 8.4
  TOP w0.254: U1.G15 v1(55.81,67.23)
  L5_SIG3 w0.102: 55.31,74.67 55.31,67.73 v1(55.81,67.23)
IO114: length 8.6
  TOP w0.254: U1.G16 v1(56.81,67.23)
  L5_SIG3 w0.102: 55.76,74.66 55.76,72.95 56.31,72.39 56.31,67.73 v1(56.81,67.23)
IO115: length 8.7
  TOP w0.254: U1.G17 v1(57.81,67.23)
  L5_SIG3 w0.102: 57.31,74.97 57.31,67.73 v1(57.81,67.23)
IO116: length 8.4
  TOP w0.254: U1.G19 v1(59.81,67.23)
  L5_SIG3 w0.102: 59.31,74.67 59.31,67.73 v1(59.81,67.23)
IO117: length 8.1
  TOP w0.254: U1.G20 v1(60.81,67.23)
  L5_SIG3 w0.102: 61.31,74.4 61.31,67.73 v1(60.81,67.23)
IO118: length 8.2
  TOP w0.254: U1.G21 v1(61.81,67.23)
  L5_SIG3 w0.102: 62.31,74.49 62.31,67.73 v1(61.81,67.23)
IO119: length 1.9
  TOP w0.127: U1.H1 39.42,65.73
IO120: length 3.1
  TOP w0.127: 39.42,66.23 41.81,66.23 U1.H2
IO121: length 4.4
  TOP w0.254: U1.H3 v1(42.81,66.23)
  L3_SIG1 w0.102: v1(42.81,66.23) 39.09,66.23
IO122: length 5.6
  TOP w0.254: U1.H4 v1(43.81,66.23)
  L3_SIG1 w0.102: v1(43.81,66.23) 43.31,66.73 39.09,66.73
IO123: length 8.4
  TOP w0.254: U1.H6 v1(45.81,66.23)
  L5_SIG3 w0.102: v1(45.81,66.23) 45.52,66.23 45.02,66.73 38.37,66.73
IO124: length 10
  TOP w0.254: U1.H7 v1(46.81,66.23)
  L5_SIG3 w0.102: 38.66,67.17 41.27,67.17 41.83,67.73 45.02,67.73 45.31,67.44 45.31,66.98 45.56,66.73 46.02,66.73 46.52,66.23 v1(46.81,66.23)
IO125: length 9.6
  TOP w0.254: U1.H8 v1(47.81,66.23)
  L5_SIG3 w0.102: v1(47.81,66.23) 47.54,66.23 47.04,66.73 46.61,66.73 46.31,67.03 46.31,67.44 46.02,67.73 45.61,67.73 45.31,68.03 45.31,68.44 45.02,68.73 40.48,68.73
IO126: length 9.8
  TOP w0.254: U1.H9 v1(48.81,66.23)
  L5_SIG3 w0.102: v1(48.81,66.23) 48.81,66.53 48.31,67.03 48.31,67.49 48.07,67.73 47.61,67.73 47.31,68.03 47.31,74.48
IO127: length 9.8
  TOP w0.254: U1.H11 v1(50.81,66.23)
  L6_SIG4 w0.102: 50.31,75.11 50.31,67.03 50.81,66.53 v1(50.81,66.23)
IO128: length 9.8
  TOP w0.254: U1.H12 v1(51.81,66.23)
  L6_SIG4 w0.102: v1(51.81,66.23) 52.31,66.73 52.31,75.11
IO129: length 9.4
  TOP w0.254: U1.H13 v1(52.81,66.23)
  L5_SIG3 w0.102: v1(52.81,66.23) 53.31,66.73 53.31,74.67
IO130: length 8.4
  TOP w0.254: U1.H14 v1(53.81,66.23)
  L5_SIG3 w0.102: v1(53.81,66.23) 54.31,66.73 54.31,73.67
IO131: length 9.4
  TOP w0.254: U1.H16 v1(56.81,66.23)
  L6_SIG4 w0.102: 55.65,74.42 55.65,72.86 56.31,72.19 56.31,66.73 v1(56.81,66.23)
IO132: length 7.7
  TOP w0.254: U1.H17 v1(57.81,66.23)
  L6_SIG4 w0.102: v1(57.81,66.23) 58.31,66.73 58.31,72.99
IO133: length 9.8
  TOP w0.254: U1.H18 v1(58.81,66.23)
  L6_SIG4 w0.102: v1(58.81,66.23) 58.81,66.51 59.31,67.01 59.31,75.11
IO134: length 7.6
  TOP w0.254: U1.H19 v1(59.81,66.23)
  L5_SIG3 w0.102: v1(59.81,66.23) 60.31,66.73 60.31,72.93
IO135: length 9.8
  TOP w0.254: U1.H21 v1(61.81,66.23)
  L5_SIG3 w0.102: v1(61.81,66.23) 62.31,66.73 63.02,66.73 63.31,67.03 63.31,74.29
IO136: length 1.9
  TOP w0.127: U1.J1 39.42,64.73
IO137: length 4.6
  TOP w0.254: U1.J3 v1(42.81,65.23)
  L3_SIG1 w0.102: v1(42.81,65.23) 42.31,64.73 39.1,64.73
IO138: length 5.6
  TOP w0.254: U1.J4 v1(43.81,65.23)
  L3_SIG1 w0.102: 39.09,65.73 43.31,65.73 v1(43.81,65.23)
IO139: length 6.5
  TOP w0.254: U1.J5 v1(44.81,65.23)
  L4_SIG2 w0.102: v1(44.81,65.23) 44.31,65.73 39.26,65.73
IO140: length 8.4
  TOP w0.254: U1.J6 v1(45.81,65.23)
  L5_SIG3 w0.102: v1(45.81,65.23) 45.31,65.73 38.37,65.73
IO141: length 7.5
  TOP w0.254: U1.J8 v1(47.81,65.23)
  L6_SIG4 w0.102: 41.26,65.73 47.11,65.73 47.6,65.23 v1(47.81,65.23)
IO142: length 11.6
  TOP w0.254: U1.J9 v1(48.81,65.23)
  L5_SIG3 w0.102: v1(48.81,65.23) 48.81,65.5 48.31,66 48.31,66.44 48.02,66.73 47.61,66.73 47.31,67.03 47.31,67.44 47.02,67.73 46.61,67.73 46.31,68.03 46.31,72.34 46.81,72.84 46.81,74.36
IO143: length 10.6
  TOP w0.254: U1.J10 v1(49.81,65.23)
  L6_SIG4 w0.102: v1(49.81,65.23) 49.81,65.52 49.31,66.02 49.31,66.44 49.02,66.73 48.61,66.73 48.31,67.03 48.31,74.22
IO144: length 11.4
  TOP w0.254: U1.J11 v1(50.81,65.23)
  L6_SIG4 w0.102: 49.31,75.07 49.31,67.03 49.61,66.73 50.02,66.73 50.31,66.44 50.31,65.73 v1(50.81,65.23)
IO145: length 11
  TOP w0.254: U1.J12 v1(51.81,65.23)
  L6_SIG4 w0.102: 50.67,75.02 50.67,72.8 51.31,72.16 51.31,65.73 v1(51.81,65.23)
IO146: length 10.9
  TOP w0.254: U1.J13 v1(52.81,65.23)
  L6_SIG4 w0.102: v1(52.81,65.23) 53.06,65.23 53.56,65.73 54.3,65.73 54.58,66.01 54.58,74.11
IO147: length 9.3
  TOP w0.254: U1.J14 v1(53.81,65.23)
  L5_SIG3 w0.102: v1(53.81,65.23) 54.64,66.06 54.64,73.5
IO148: length 10
  TOP w0.254: U1.J15 v1(55.81,65.23)
  L5_SIG3 w0.102: 54.82,74.11 54.97,73.96 54.97,66.07 v1(55.81,65.23)
IO149: length 10.4
  TOP w0.254: U1.J16 v1(56.81,65.23)
  L6_SIG4 w0.102: v1(56.81,65.23) 56.31,65.73 55.58,65.73 55.08,66.23 55.08,73.79
IO150: length 10.5
  TOP w0.254: U1.J18 v1(58.81,65.23)
  L6_SIG4 w0.102: v1(58.81,65.23) 58.81,65.52 59.31,66.02 59.31,66.44 59.61,66.73 60.02,66.73 60.31,67.03 60.31,74.13
IO151: length 10.3
  TOP w0.254: U1.J19 v1(59.81,65.23)
  L5_SIG3 w0.102: v1(59.81,65.23) 60.11,65.23 60.61,65.73 69.17,65.73
IO152: length 10
  TOP w0.254: U1.J20 v1(60.81,65.23)
  L4_SIG2 w0.102: v1(60.81,65.23) 61.31,64.73 69.91,64.73
IO153: length 10.4
  TOP w0.254: U1.J21 v1(61.81,65.23)
  L4_SIG2 w0.102: v1(61.81,65.23) 62.31,65.73 63.02,65.73 63.31,66.03 63.31,66.44 63.61,66.73 65.02,66.73 65.31,67.03 65.31,67.44 65.61,67.73 70.02,67.73
IO154: length 1.9
  TOP w0.127: U1.K1 39.42,63.73
IO155: length 3.1
  TOP w0.127: 39.42,64.23 41.81,64.23 U1.K2
IO156: length 4.3
  TOP w0.254: U1.K3 v1(42.81,64.23)
  L3_SIG1 w0.102: 39.25,64.23 v1(42.81,64.23)
IO157: length 6.5
  TOP w0.254: U1.K5 v1(44.81,64.23)
  L4_SIG2 w0.102: v1(44.81,64.23) 44.31,64.73 39.26,64.73
IO158: length 7.5
  TOP w0.254: U1.K6 v1(45.81,64.23)
  L4_SIG2 w0.102: 39.26,63.73 45.31,63.73 v1(45.81,64.23)
IO159: length 9.4
  TOP w0.254: U1.K7 v1(46.81,64.23)
  L5_SIG3 w0.102: v1(46.81,64.23) 46.31,64.73 38.37,64.73
IO160: length 8.8
  TOP w0.254: U1.K8 v1(47.81,64.23)
  L6_SIG4 w0.102: 39.91,64.73 47.33,64.73 47.81,64.24 v1(47.81,64.23)
IO161: length 12.3
  TOP w0.254: U1.K10 v1(49.81,64.23)
  L6_SIG4 w0.102: 47.31,74.31 47.31,67.03 47.61,66.73 48.02,66.73 48.31,66.44 48.31,66.03 48.61,65.73 49.02,65.73 49.31,65.44 49.31,64.73 v1(49.81,64.23)
IO162: length 12.4
  TOP w0.254: U1.K12 v1(51.81,64.23)
  L6_SIG4 w0.102: v1(51.81,64.23) 52.31,64.73 52.31,65.44 52.61,65.73 53.02,65.73 53.31,66.03 53.31,75.11
IO163: length 11.5
  TOP w0.254: U1.K16 v1(56.81,64.23)
  L6_SIG4 w0.102: 57.31,74.84 57.31,64.73 v1(56.81,64.23)
IO164: length 13.3
  TOP w0.254: U1.K17 v1(57.81,64.23)
  L6_SIG4 w0.102: 61.31,74.47 61.31,67.03 61.02,66.73 60.61,66.73 60.31,66.44 60.31,65.94 60.1,65.73 59.61,65.73 59.31,65.44 59.31,65.03 59.02,64.73 58.29,64.73 57.81,64.26 v1(57.81,64.23)
IO165: length 10.6
  TOP w0.254: U1.K18 v1(58.81,64.23)
  L5_SIG3 w0.102: 68.54,63.73 59.31,63.73 v1(58.81,64.23)
IO166: length 10.1
  TOP w0.254: U1.K19 v1(59.81,64.23)
  L5_SIG3 w0.102: v1(59.81,64.23) 60.31,64.73 69.01,64.73
IO167: length 3.1
  TOP w0.127: U1.L2 41.82,63.23 39.47,63.23
IO168: length 4.3
  TOP w0.254: U1.L3 v1(42.81,63.23)
  L3_SIG1 w0.102: v1(42.81,63.23) 39.21,63.23
IO169: length 5.8
  TOP w0.254: U1.L4 v1(43.81,63.23)
  L3_SIG1 w0.102: 39.14,62.17 41.96,62.17 42.52,62.73 43.31,62.73 v1(43.81,63.23)
IO170: length 6.5
  TOP w0.254: U1.L5 v1(44.81,63.23)
  L3_SIG1 w0.102: v1(44.81,63.23) 44.32,63.73 39.19,63.73
IO171: length 8.4
  TOP w0.254: U1.L7 v1(46.81,63.23)
  L5_SIG3 w0.102: 39.37,63.73 46.31,63.73 v1(46.81,63.23)
IO172: length 9.5
  TOP w0.254: U1.L8 v1(47.81,63.23)
  L6_SIG4 w0.102: 39.25,63.73 47.31,63.73 v1(47.81,63.23)
IO173: length 11.4
  TOP w0.254: U1.L9 v1(48.81,63.23)
  L6_SIG4 w0.102: 40.78,66.73 47.02,66.73 47.31,66.44 47.31,66.03 47.61,65.73 48.02,65.73 48.31,65.44 48.31,63.73 v1(48.81,63.23)
IO174: length 0.7
  TOP w0.254: U1.L10 v1(49.81,63.23)
  L6_SIG4 w0.102: 49.81,63.26 v1(49.81,63.23)
IO175: length 1.9
  TOP w0.127: U1.M1 39.42,61.73
IO176: length 3.1
  TOP w0.127: 39.42,62.23 41.81,62.23 U1.M2
IO177: length 5.6
  TOP w0.254: U1.M4 v1(43.81,62.23)
  L3_SIG1 w0.102: v1(43.81,62.23) 43.31,61.73 39.14,61.73
IO178: length 6.6
  TOP w0.254: U1.M5 v1(44.81,62.23)
  L4_SIG2 w0.102: v1(44.81,62.23) 44.31,62.73 41.56,62.73 41.07,63.23 39.32,63.23
IO179: length 7.6
  TOP w0.254: U1.M6 v1(45.81,62.23)
  L5_SIG3 w0.102: v1(45.81,62.23) 45.31,62.73 41.47,62.73 40.87,62.13 39.34,62.13
IO180: length 8.4
  TOP w0.254: U1.M7 v1(46.81,62.23)
  L5_SIG3 w0.102: 39.37,61.73 46.31,61.73 v1(46.81,62.23)
IO181: length 11
  TOP w0.254: U1.M9 v1(48.81,62.23)
  L6_SIG4 w0.102: v1(48.81,62.23) 48.31,62.73 41.55,62.73 41,63.28 38.99,63.28
IO182: length 11.8
  TOP w0.254: U1.M10 v1(49.81,62.23)
  L6_SIG4 w0.102: 38.93,61.73 49.31,61.73 v1(49.81,62.23)
IO183: length 1.9
  TOP w0.127: U1.N1 39.42,60.73
IO184: length 3.1
  TOP w0.127: 39.42,61.23 41.81,61.23 U1.N2
IO185: length 4.4
  TOP w0.254: U1.N3 v1(42.81,61.23)
  L3_SIG1 w0.102: v1(42.81,61.23) 39.14,61.23
IO186: length 5.6
  TOP w0.254: U1.N4 v1(43.81,61.23)
  L3_SIG1 w0.102: v1(43.81,61.23) 43.31,60.73 39.14,60.73
IO187: length 7.5
  TOP w0.254: U1.N6 v1(45.81,61.23)
  L4_SIG2 w0.102: 39.26,61.73 45.31,61.73 v1(45.81,61.23)
IO188: length 9.1
  TOP w0.254: U1.N7 v1(46.81,61.23)
  L4_SIG2 w0.102: v1(46.81,61.23) 46.31,60.73 46.31,59.72 46,59.4 39.8,59.4
IO189: length 8.4
  TOP w0.254: U1.N8 v1(47.81,61.23)
  L5_SIG3 w0.102: 40.37,60.73 47.31,60.73 v1(47.81,61.23)
IO190: length 9.8
  TOP w0.254: U1.N9 v1(48.81,61.23)
  L6_SIG4 w0.102: v1(48.81,61.23) 48.31,60.73 39.93,60.73
IO191: length 10.1
  TOP w0.254: U1.N10 v1(49.81,61.23)
  L6_SIG4 w0.102: v1(49.81,61.23) 49.31,60.73 49.31,60.03 49.01,59.72 41.42,59.72
IO192: length 1.8
  TOP w0.127: U1.P1 39.5,59.73
IO193: length 4.5
  TOP w0.254: U1.P3 v1(42.81,60.23)
  L3_SIG1 w0.102: v1(42.81,60.23) 42.3,59.72 39.25,59.72
IO194: length 5.6
  TOP w0.254: U1.P4 v1(43.81,60.23)
  L3_SIG1 w0.102: 39.3,59.21 42.79,59.21 v1(43.81,60.23)
IO195: length 6.5
  TOP w0.254: U1.P5 v1(44.81,60.23)
  L4_SIG2 w0.102: v1(44.81,60.23) 44.31,60.73 39.26,60.73
IO196: length 7.5
  TOP w0.254: U1.P6 v1(45.81,60.23)
  L4_SIG2 w0.102: 39.26,59.73 45.31,59.73 v1(45.81,60.23)
IO197: length 8.4
  TOP w0.254: U1.P8 v1(47.81,60.23)
  L5_SIG3 w0.102: 40.37,59.72 47.3,59.72 v1(47.81,60.23)
IO198: length 9.5
  TOP w0.254: U1.P9 v1(48.81,60.23)
  L5_SIG3 w0.102: v1(48.81,60.23) 47.97,59.39 40.41,59.39
IO199: length 9.7
  TOP w0.254: U1.P10 v1(49.81,60.23)
  L6_SIG4 w0.102: v1(49.81,60.23) 49.81,59.99 49.21,59.39 41.27,59.39
IO200: length 1.8
  TOP w0.127: U1.R1 39.5,58.73
IO201: length 3
  TOP w0.127: U1.R2 41.81,59.23 39.5,59.23
IO202: length 4.3
  TOP w0.254: U1.R3 v1(42.81,58.23)
  L3_SIG1 w0.102: v1(42.81,58.23) 39.25,58.23
IO203: length 6.5
  TOP w0.254: U1.R5 v1(44.81,58.23)
  L3_SIG1 w0.102: 39.29,58.79 44.26,58.79 v1(44.81,58.23)
IO204: length 7.5
  TOP w0.254: U1.R6 v1(45.81,58.23)
  L4_SIG2 w0.102: v1(45.81,58.23) 45.31,58.73 39.26,58.73
IO205: length 8.4
  TOP w0.254: U1.R7 v1(46.81,58.23)
  L4_SIG2 w0.102: 39.46,59.07 45.98,59.07 v1(46.81,58.23)
IO206: length 8.3
  TOP w0.254: U1.R8 v1(47.81,58.23)
  L5_SIG3 w0.102: v1(47.81,58.23) 47.31,58.73 40.47,58.73
IO207: length 10.6
  TOP w0.254: U1.R10 v1(49.81,58.23)
  L6_SIG4 w0.102: 40.58,59.06 49.46,59.06 49.81,58.71 v1(49.81,58.23)
IO208: length 3
  TOP w0.127: U1.T2 41.81,58.23 39.5,58.23
IO209: length 4
  TOP w0.127: U1.T3 42.83,57.25 39.52,57.25
IO210: length 5.6
  TOP w0.254: U1.T4 v1(43.81,57.23)
  L3_SIG1 w0.102: 39.14,56.78 41.61,56.78 42.06,57.23 v1(43.81,57.23)
IO211: length 6.8
  TOP w0.254: U1.T5 v1(44.81,57.23)
  L3_SIG1 w0.102: 39.17,57.22 41.08,57.22 41.59,57.73 44.32,57.73 v1(44.81,57.23)
IO212: length 8.5
  TOP w0.254: U1.T7 v1(46.81,57.23)
  L4_SIG2 w0.102: 39.44,58.23 40.98,58.23 41.48,57.73 46.31,57.73 v1(46.81,57.23)
IO213: length 9.9
  TOP w0.254: U1.T8 v1(47.81,57.23)
  L5_SIG3 w0.102: v1(47.81,57.23) 47.31,57.73 41.87,57.73 41.32,57.19 39.03,57.19
IO214: length 10.5
  TOP w0.254: U1.T9 v1(48.81,57.23)
  L5_SIG3 w0.102: v1(48.81,57.23) 48.31,57.73 48.31,58.72 47.97,59.06 40.34,59.06
IO215: length 10.8
  TOP w0.254: U1.T10 v1(49.81,57.23)
  L6_SIG4 w0.102: 40.76,58.73 49.02,58.73 49.31,58.44 49.31,57.73 v1(49.81,57.23)
IO216: length 1.8
  TOP w0.127: U1.U1 39.5,56.73
IO217: length 3
  TOP w0.127: U1.U2 41.81,56.23 39.5,56.23
IO218: length 5.9
  TOP w0.254: U1.U4 v1(43.81,56.23)
  L3_SIG1 w0.102: 39.02,56.3 41.97,56.3 42.39,56.73 43.31,56.73 v1(43.81,56.23)
IO219: length 6.5
  TOP w0.254: U1.U5 v1(44.81,56.23)
  L4_SIG2 w0.102: 39.26,56.73 44.31,56.73 v1(44.81,56.23)
IO220: length 7.4
  TOP w0.254: U1.U6 v1(45.81,56.23)
  L4_SIG2 w0.102: 39.36,55.73 45.31,55.73 v1(45.81,56.23)
IO221: length 9.4
  TOP w0.254: U1.U7 v1(46.81,56.23)
  L5_SIG3 w0.102: v1(46.81,56.23) 46.31,56.73 38.37,56.73
IO222: length 11.6
  TOP w0.254: U1.U9 v1(48.81,56.23)
  L6_SIG4 w0.102: v1(48.81,56.23) 48.31,56.73 48.31,57.44 48.02,57.73 41.87,57.73 41.26,57.12 39.24,57.12
IO223: length 1.8
  TOP w0.127: U1.V1 39.5,55.73
IO224: length 3
  TOP w0.127: 39.5,55.23 41.81,55.23 U1.V2
IO225: length 4.5
  TOP w0.254: U1.V3 v1(42.81,55.23)
  L3_SIG1 w0.102: v1(42.81,55.23) 39.05,55.23
IO226: length 5.7
  TOP w0.254: U1.V4 v1(43.81,55.23)
  L3_SIG1 w0.102: v1(43.81,55.23) 43.31,55.73 39.01,55.73
IO227: length 8.4
  TOP w0.254: U1.V6 v1(45.81,55.23)
  L5_SIG3 w0.102: v1(45.81,55.23) 45.31,55.73 38.37,55.73
IO228: length 8.4
  TOP w0.254: U1.V7 v1(46.81,55.23)
  L5_SIG3 w0.102: 39.37,54.73 46.31,54.73 v1(46.81,55.23)
IO229: length 9.8
  TOP w0.254: U1.V8 v1(47.81,55.23)
  L6_SIG4 w0.102: v1(47.81,55.23) 47.64,55.23 47.14,55.73 38.93,55.73
IO230: length 11.1
  TOP w0.254: U1.V9 v1(48.81,55.23)
  L6_SIG4 w0.102: v1(48.81,55.23) 48.31,55.73 47.61,55.73 47.31,56.03 47.31,56.44 47.02,56.73 39.26,56.73
IO231: length 9.8
  TOP w0.254: U1.V10 v1(49.81,55.23)
  L6_SIG4 w0.102: v1(49.81,55.23) 49.31,54.73 40.91,54.73
IO232: length 1.8
  TOP w0.127: U1.W1 39.5,54.73
IO233: length 4.6
  TOP w0.254: U1.W3 v1(42.81,54.23)
  L3_SIG1 w0.102: 39.11,53.73 42.31,53.73 v1(42.81,54.23)
IO234: length 5.7
  TOP w0.254: U1.W4 v1(43.81,54.23)
  L3_SIG1 w0.102: 38.98,54.73 43.31,54.73 v1(43.81,54.23)
IO235: length 6.5
  TOP w0.254: U1.W5 v1(44.81,54.23)
  L4_SIG2 w0.102: v1(44.81,54.23) 44.31,54.73 39.26,54.73
IO236: length 7.5
  TOP w0.254: U1.W6 v1(45.81,54.23)
  L4_SIG2 w0.102: 39.23,53.73 45.31,53.73 v1(45.81,54.23)
IO237: length 9.1
  TOP w0.254: U1.W8 v1(47.81,54.23)
  L5_SIG3 w0.102: 39.61,53.73 47.31,53.73 v1(47.81,54.23)
IO238: length 11.8
  TOP w0.254: U1.W9 v1(48.81,54.23)
  L6_SIG4 w0.102: v1(48.81,54.23) 48.55,54.23 48.04,53.73 37.93,53.73
IO239: length 12.2
  TOP w0.254: U1.W10 v1(49.81,54.23)
  L6_SIG4 w0.102: 45.31,45.78 45.31,50.44 45.61,50.73 46.02,50.73 46.31,51.03 46.31,51.44 46.61,51.73 47.02,51.73 47.31,52.03 47.31,52.44 47.61,52.73 48.02,52.73 48.31,53.03 48.31,53.44 48.61,53.73 49.31,53.73 v1(49.81,54.23)
IO240: length 12.5
  TOP w0.254: U1.W12 v1(51.81,54.23)
  L6_SIG4 w0.102: 47.31,45.47 47.31,50.44 47.61,50.73 48.02,50.73 48.31,51.03 48.31,51.44 48.61,51.73 49.02,51.73 49.31,52.03 49.31,52.44 49.61,52.73 50.05,52.73 50.31,52.99 50.31,53.44 50.61,53.73 51.31,53.73 v1(51.81,54.23)
IO241: length 9.3
  TOP w0.254: U1.W13 v1(52.81,54.23)
  L6_SIG4 w0.102: v1(52.81,54.23) 52.31,53.73 52.31,45.83
IO242: length 9.4
  TOP w0.254: U1.W14 v1(53.81,54.23)
  L6_SIG4 w0.102: v1(53.81,54.23) 54.33,53.72 54.33,48.34 54.31,48.33 54.31,45.78
IO243: length 10.3
  TOP w0.254: U1.W15 v1(55.81,54.23)
  L6_SIG4 w0.102: 57.31,45.46 57.31,50.44 57.02,50.73 56.61,50.73 56.31,51.03 56.31,53.73 v1(55.81,54.23)
IO244: length 15.4
  TOP w0.254: U1.W16 v1(56.81,54.23)
  L5_SIG3 w0.102: 69.63,56.73 58.61,56.73 58.31,56.44 58.31,55.03 58.02,54.73 57.31,54.73 v1(56.81,54.23)
IO245: length 12.7
  TOP w0.254: U1.W18 v1(58.81,54.23)
  L5_SIG3 w0.102: 69.73,55.73 59.58,55.73 59.31,55.46 59.31,54.73 v1(58.81,54.23)
IO246: length 10.7
  TOP w0.254: U1.W19 v1(59.81,54.23)
  L5_SIG3 w0.102: v1(59.81,54.23) 60.31,54.73 69.61,54.73
IO247: length 10
  TOP w0.254: U1.W20 v1(60.81,54.23)
  L4_SIG2 w0.102: 69.93,53.73 61.31,53.73 v1(60.81,54.23)
IO248: length 1.8
  TOP w0.127: U1.Y1 39.5,53.73
IO249: length 3
  TOP w0.127: U1.Y2 41.81,53.23 39.5,53.23
IO250: length 4.4
  TOP w0.254: U1.Y3 v1(42.81,53.23)
  L3_SIG1 w0.102: v1(42.81,53.23) 39.11,53.23
IO251: length 6.8
  TOP w0.254: U1.Y5 v1(44.81,53.23)
  L3_SIG1 w0.102: 39.12,52.24 41.19,52.24 41.69,52.74 44.32,52.74 v1(44.81,53.23)
IO252: length 7.6
  TOP w0.254: U1.Y6 v1(45.81,53.23)
  L5_SIG3 w0.102: 39.39,52.09 40.9,52.09 41.55,52.73 45.02,52.73 45.52,53.23 v1(45.81,53.23)
IO253: length 9
  TOP w0.254: U1.Y7 v1(46.81,53.23)
  L5_SIG3 w0.102: 39.46,51.43 41.34,51.43 41.65,51.73 45.02,51.73 45.31,52.03 45.31,52.44 45.61,52.73 46.31,52.73 v1(46.81,53.23)
IO254: length 10.1
  TOP w0.254: U1.Y8 v1(47.81,53.23)
  L6_SIG4 w0.102: v1(47.81,53.23) 47.55,53.23 47.04,52.73 41.55,52.73 40.87,52.05 38.91,52.05
IO255: length 11
  TOP w0.254: U1.Y10 v1(49.81,53.23)
  L6_SIG4 w0.102: v1(49.81,53.23) 49.6,53.23 49.1,52.73 48.61,52.73 48.31,52.44 48.31,51.94 48.1,51.73 47.61,51.73 47.31,51.44 47.31,51.03 47.02,50.73 46.61,50.73 46.31,50.44 46.31,45.35
IO256: length 10.5
  TOP w0.254: U1.Y11 v1(50.81,53.23)
  L6_SIG4 w0.102: 48.31,44.98 48.31,50.44 48.61,50.73 49.02,50.73 49.31,51.03 49.31,51.44 49.61,51.73 50.02,51.73 50.31,52.03 50.31,52.47 50.81,52.97 v1(50.81,53.23)
IO257: length 9.8
  TOP w0.254: U1.Y12 v1(51.81,53.23)
  L6_SIG4 w0.102: 49.31,45.8 49.31,50.44 49.61,50.73 50.02,50.73 50.31,51.03 50.31,51.52 50.52,51.73 51.11,51.73 51.31,51.94 51.31,52.73 v1(51.81,53.23)
IO258: length 8.3
  TOP w0.254: U1.Y13 v1(52.81,53.23)
  L6_SIG4 w0.102: v1(52.81,53.23) 53.31,52.73 53.31,45.83
IO259: length 8.5
  TOP w0.254: U1.Y15 v1(55.81,53.23)
  L6_SIG4 w0.102: 55.31,46.02 55.31,49.56 54.83,50.05 54.83,52.25 v1(55.81,53.23)
IO260: length 9.3
  TOP w0.254: U1.Y16 v1(56.81,53.23)
  L6_SIG4 w0.102: v1(56.81,53.23) 57.31,52.73 57.31,51.03 57.61,50.73 58.02,50.73 58.31,50.44 58.31,45.46
IO261: length 12.8
  TOP w0.254: U1.Y17 v1(57.81,53.23)
  L5_SIG3 w0.102: v1(57.81,53.23) 58.31,53.73 69.74,53.73
IO262: length 11.9
  TOP w0.254: U1.Y18 v1(58.81,53.23)
  L5_SIG3 w0.102: v1(58.81,53.23) 59.31,52.74 69.76,52.74
IO263: length 12.3
  TOP w0.254: U1.Y20 v1(60.81,53.23)
  L4_SIG2 w0.102: v1(60.81,53.23) 61.31,52.73 62.02,52.73 62.31,52.44 62.31,52.03 62.61,51.73 64.02,51.73 64.31,51.44 64.31,51.02 64.61,50.73 65.02,50.73 65.31,50.44 65.31,50.01 65.59,49.73 70.22,49.73
IO264: length 9.1
  TOP w0.254: U1.Y21 v1(61.81,53.23)
  L4_SIG2 w0.102: 69.97,52.73 62.52,52.73 62.02,53.23 v1(61.81,53.23)
IO265: length 3
  TOP w0.127: 39.53,52.25 41.83,52.25 U1.AA2
IO266: length 4.6
  TOP w0.254: U1.AA3 v1(42.81,52.23)
  L3_SIG1 w0.102: v1(42.81,52.23) 41.97,52.23 41.47,51.72 39.11,51.72
IO267: length 5.8
  TOP w0.254: U1.AA4 v1(43.81,52.23)
  L3_SIG1 w0.102: v1(43.81,52.23) 43.31,51.73 42.52,51.73 42,51.21 39.11,51.21
IO268: length 6.7
  TOP w0.254: U1.AA5 v1(44.81,52.23)
  L4_SIG2 w0.102: v1(44.81,52.23) 44.31,52.73 41.5,52.73 40.99,53.24 39.27,53.24
IO269: length 8.7
  TOP w0.254: U1.AA7 v1(46.81,52.23)
  L5_SIG3 w0.102: v1(46.81,52.23) 46.52,52.23 46.02,51.73 45.61,51.73 45.31,51.44 45.31,51.03 45.02,50.73 39.64,50.73
IO270: length 8.9
  TOP w0.254: U1.AA8 v1(47.81,52.23)
  L5_SIG3 w0.102: v1(47.81,52.23) 47.52,52.23 47.02,51.73 46.61,51.73 46.31,51.44 46.31,51.03 46.02,50.73 45.61,50.73 45.31,50.44 45.31,45.71
IO271: length 9.5
  TOP w0.254: U1.AA9 v1(48.81,52.23)
  L5_SIG3 w0.102: v1(48.81,52.23) 48.52,52.23 48.02,51.73 47.52,51.73 47.31,51.52 47.31,51.03 47.02,50.73 46.61,50.73 46.31,50.44 46.31,45.22
IO272: length 10
  TOP w0.254: U1.AA10 v1(49.81,52.23)
  L5_SIG3 w0.102: v1(49.81,52.23) 49.31,51.73 48.61,51.73 48.31,51.44 48.31,51.03 48.02,50.73 47.59,50.73 47.31,50.46 47.31,44.6
IO273: length 8.3
  TOP w0.254: U1.AA12 v1(51.81,52.23)
  L6_SIG4 w0.102: v1(51.81,52.23) 51.81,51.94 51.31,51.44 51.31,51.24 51.31,51.23 51.31,44.83
IO274: length 10.4
  TOP w0.254: U1.AA13 v1(52.81,52.23)
  L5_SIG3 w0.102: v1(52.81,52.23) 52.31,51.73 52.31,42.79
IO275: length 10.4
  TOP w0.254: U1.AA14 v1(53.81,52.23)
  L5_SIG3 w0.102: v1(53.81,52.23) 53.31,51.73 53.31,42.79
IO276: length 8.3
  TOP w0.254: U1.AA15 v1(55.81,52.23)
  L6_SIG4 w0.102: v1(55.81,52.23) 55.31,51.73 55.31,51.03 55.61,50.73 56.02,50.73 56.31,50.44 56.31,45.53
IO277: length 8.4
  TOP w0.254: U1.AA17 v1(57.81,52.23)
  L6_SIG4 w0.102: v1(57.81,52.23) 58.31,51.73 59.02,51.73 59.31,51.44 59.31,45.6
IO278: length 8.3
  TOP w0.254: U1.AA18 v1(58.81,52.23)
  L6_SIG4 w0.102: v1(58.81,52.23) 58.99,52.23 59.49,51.73 60.02,51.73 60.31,51.44 60.31,45.68
IO279: length 9.7
  TOP w0.254: U1.AA19 v1(59.81,52.23)
  L5_SIG3 w0.102: 61.31,44.09 61.31,49.44 61.02,49.73 60.61,49.73 60.31,50.03 60.31,51.73 v1(59.81,52.23)
IO280: length 12.4
  TOP w0.254: U1.AA20 v1(60.81,52.23)
  L4_SIG2 w0.102: v1(60.81,52.23) 61.31,51.73 62.02,51.73 62.31,51.44 62.31,51.03 62.61,50.73 63.02,50.73 63.31,50.44 63.31,49.98 63.56,49.73 65.02,49.73 65.31,49.44 65.31,49.03 65.61,48.73 70.28,48.73
IO281: length 1.8
  TOP w0.127: U1.AB1 39.5,51.73
IO282: length 3
  TOP w0.127: U1.AB2 41.81,51.23 39.5,51.23
IO283: length 5.6
  TOP w0.254: U1.AB4 v1(43.81,51.23)
  L3_SIG1 w0.102: v1(43.81,51.23) 43.31,50.73 39.11,50.73
IO284: length 6.5
  TOP w0.254: U1.AB5 v1(44.81,51.23)
  L4_SIG2 w0.102: v1(44.81,51.23) 44.31,51.73 39.26,51.73
IO285: length 7.5
  TOP w0.254: U1.AB6 v1(45.81,51.23)
  L4_SIG2 w0.102: 39.26,50.73 45.31,50.73 v1(45.81,51.23)
IO286: length 9.7
  TOP w0.254: U1.AB7 v1(46.81,51.23)
  L4_SIG2 w0.102: 39.55,48.73 45.02,48.73 45.31,49.03 45.31,49.52 45.52,49.73 46.02,49.73 46.31,50.03 46.31,50.73 v1(46.81,51.23)
IO287: length 7.6
  TOP w0.254: U1.AB9 v1(48.81,51.23)
  L5_SIG3 w0.102: 48.31,44.55 48.31,50.46 48.81,50.96 v1(48.81,51.23)
IO288: length 8.4
  TOP w0.254: U1.AB10 v1(49.81,51.23)
  L5_SIG3 w0.102: 49.31,43.79 49.31,50.73 v1(49.81,51.23)
IO289: length 6.3
  TOP w0.254: U1.AB11 v1(50.81,51.23)
  L6_SIG4 w0.102: 50.31,45.81 50.31,50.52 50.81,51.02 v1(50.81,51.23)
IO290: length 8.4
  TOP w0.254: U1.AB12 v1(51.81,51.23)
  L5_SIG3 w0.102: v1(51.81,51.23) 51.31,50.73 51.31,43.79
IO291: length 8.4
  TOP w0.254: U1.AB14 v1(53.81,51.23)
  L5_SIG3 w0.102: 54.31,43.79 54.31,50.73 v1(53.81,51.23)
IO292: length 8.5
  TOP w0.254: U1.AB15 v1(55.81,51.23)
  L5_SIG3 w0.102: v1(55.81,51.23) 55.31,50.73 55.31,46.17 54.73,45.59 54.73,43.89
IO293: length 8.4
  TOP w0.254: U1.AB16 v1(56.81,51.23)
  L5_SIG3 w0.102: v1(56.81,51.23) 56.31,50.73 56.31,43.75
IO294: length 8
  TOP w0.254: U1.AB17 v1(57.81,51.23)
  L5_SIG3 w0.102: v1(57.81,51.23) 58.31,50.73 58.31,44.15
IO295: length 9
  TOP w0.254: U1.AB19 v1(59.81,51.23)
  L5_SIG3 w0.102: v1(59.81,51.23) 59.31,50.73 59.31,50.03 59.61,49.73 60.02,49.73 60.31,49.44 60.31,46.28 60.81,45.78 60.81,44
IO296: length 8.9
  TOP w0.254: U1.AB20 v1(60.81,51.23)
  L5_SIG3 w0.102: 62.31,43.88 62.31,49.44 62.02,49.73 61.61,49.73 61.31,50.03 61.31,50.73 v1(60.81,51.23)
IO297: length 9.5
  TOP w0.254: U1.AB21 v1(61.81,51.23)
  L4_SIG2 w0.102: 62.31,43.33 62.31,47.44 62.02,47.73 61.61,47.73 61.31,48.02 61.31,50.73 v1(61.81,51.23)
IO298: length 1.8
  TOP w0.127: U1.AC1 39.5,50.73
